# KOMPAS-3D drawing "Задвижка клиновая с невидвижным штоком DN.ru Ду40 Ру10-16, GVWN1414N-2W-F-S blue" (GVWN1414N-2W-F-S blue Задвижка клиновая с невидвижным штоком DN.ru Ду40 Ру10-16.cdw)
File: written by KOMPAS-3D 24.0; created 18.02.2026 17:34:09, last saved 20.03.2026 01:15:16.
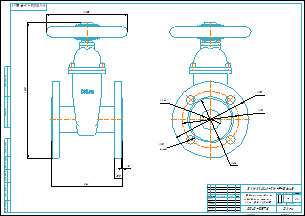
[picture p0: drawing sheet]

Document properties: Автор: R2D2; Форматы листов документа: A2; Полное имя файла: GVWN1414N-2W-F-S blue Задвижка клиновая с невидвижным штоком DN.ru Ду40 Ру10-16.m3d; Масса: 7; Наименование: Задвижка клиновая с невидвижным штоком DN.ru Ду40 Ру10-16; Количество листов документа: 1; Примечание: D040-10578

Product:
- Part/product: Задвижка клиновая с невидвижным штоком DN.ru Ду40 Ру10-16  | designation GVWN1414N-2W-F-S blue
    Масса: 7
    Раздел спецификации: Прочие изделия
    Примечание: D040-10578

Views: Вид 1, Спереди, Проекционный вид 2
Referenced files in E:\Работа\Зайцев\GVWN1414N-2W-F-S blue Задвижка клиновая с невидвижным штоком DN.ru Ду40-300 Ру10-16\DN40\: GVWN1414N-2W-F-S blue Задвижка клиновая с невидвижным штоком DN.ru Ду40 Ру10-16.m3d
Referenced files in E:\Работа\Зайцев\Для компаса\: чертеж DN.ru А3.cdt
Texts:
  GVWN1414N-2W-F-S blue
  чертеж DN.ru А3.cdt
  Задвижка клиновая с
  невидвижным штоком
  DN.ru Ду40 Ру10-16
  Задвижка клиновая с невидвижным штоком DN.ru Ду40 Ру10-16
  GVWN1414N-2W-F-S blue Задвижка клиновая с невидвижным штоком DN.ru Ду40 Ру10-16
Dimensions and other numbers on the sheet: 0; 3; 2; 4; 140; 15,5; 2,5; 265; 160; 110; 150; 84; 40; 18; 4 отв.; 1:1; 1; 7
